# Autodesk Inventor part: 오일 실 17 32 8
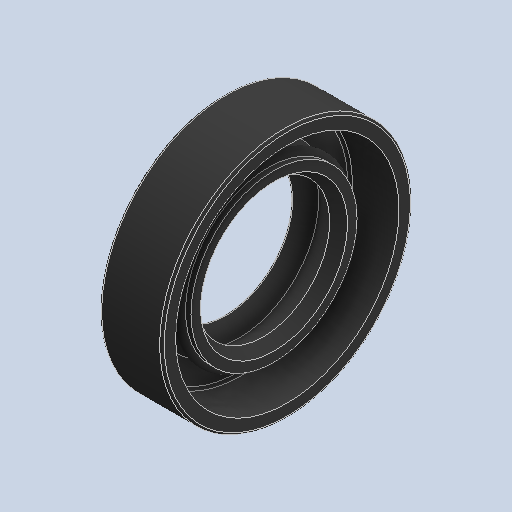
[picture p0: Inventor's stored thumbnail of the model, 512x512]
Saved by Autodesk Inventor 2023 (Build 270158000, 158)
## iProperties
Created: 2025-04
Part Number: 오일 실 17 32 8
Material: 고무
Description: 오일-실
Document SubType Name: Modeling
Designer: User
Density: 0.93 g/cm^3
Appearance: 기본값
Author: jhkim
Revision Number: 1
Sending System: Autodesk Inventor 2026
Preprocessor: ST-DEVELOPER v20.1
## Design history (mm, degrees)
feature "Solid1"
node "솔리드1"
